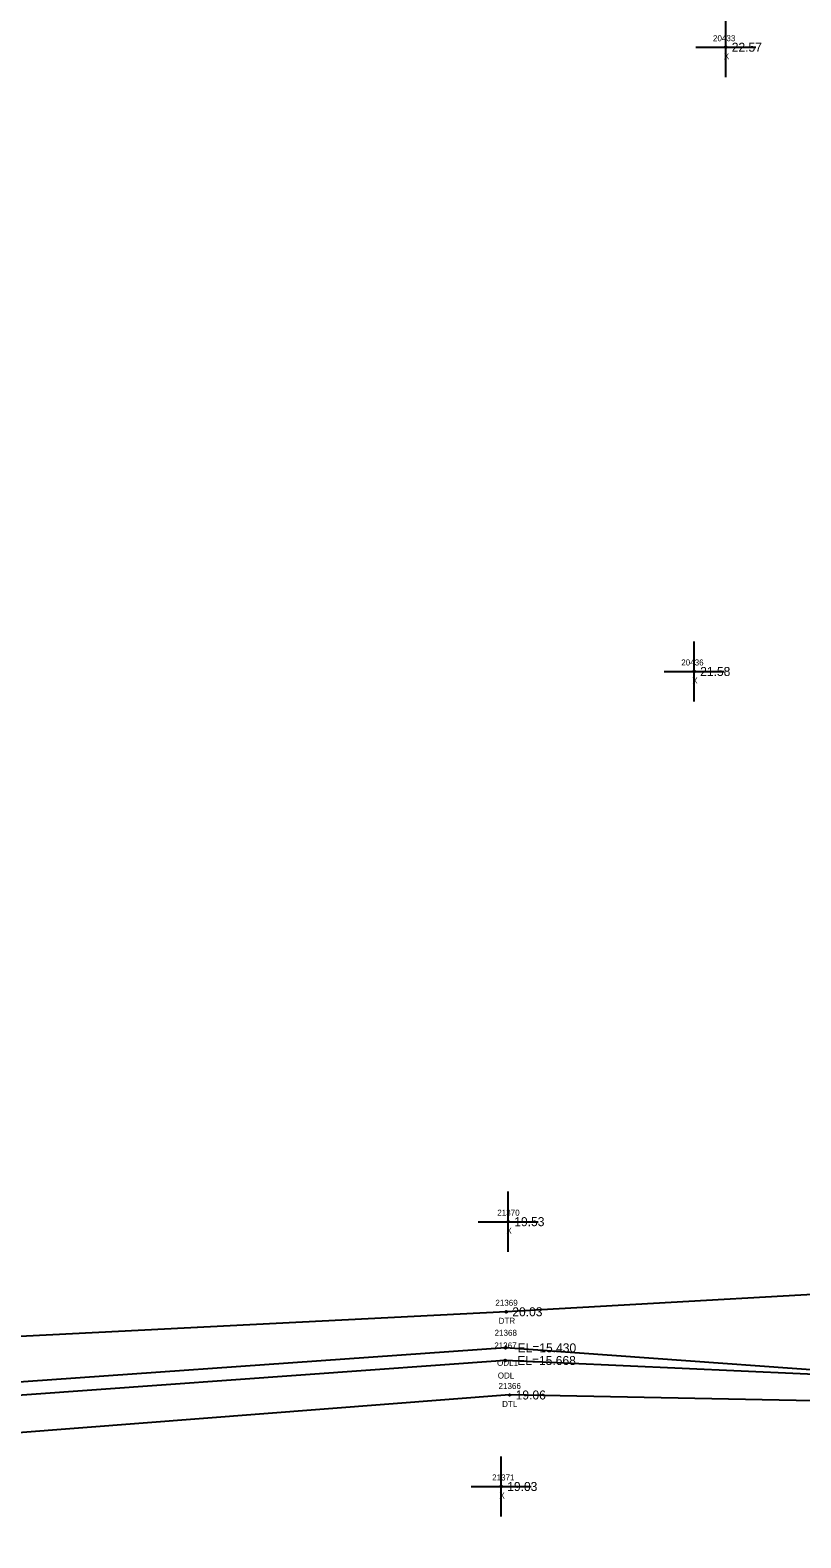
# Model space of a CAD drawing. Extents: x 2655177 to 2656219, y 761780 to 764748.
# Drawn here: x 2655601.7 to 2655730, y 763539 to 763790 of the extents above; entities that cross this region are included whole.
import ezdxf

# ---------------------------------------------------------------- set-up
doc = ezdxf.new("R2010")
doc.units = 0
for name, color, linetype in [('RD_EX_H2O', 7, 'Continuous'), ('RD_EX_H2O_txCode', 7, 'Continuous'), ('RD_EX_Misc', 7, 'Continuous'), ('RD_EX_Misc_txCode', 7, 'Continuous'), ('RD_EX_TX_H2O_ELEV', 7, 'Continuous'), ('RD_EX_TX_Misc_ELEV', 7, 'Continuous'), ('RD_SMD_Locator', 7, 'Continuous')]:
    doc.layers.add(name, color=color, linetype=linetype)

msp = doc.modelspace()

# ---------------------------------------------------------------- linework, layer by layer
at = {"layer": 'RD_EX_H2O'}
for points in [[(2655757.45, 763580.99), (2655680.96, 763576.66), (2655578.06, 763571.44), (2655470.41, 763559.47), (2655370.94, 763554.75), (2655276.75, 763546.33)], [(2655759.35, 763565.01), (2655680.83, 763570.66), (2655578.54, 763563.45), (2655471.45, 763555.87), (2655371.16, 763549.76), (2655277.06, 763543.35)], [(2655759.35, 763565.01), (2655680.78, 763568.55), (2655578.67, 763561.21), (2655471.72, 763553.89), (2655371.24, 763547.95), (2655277.37, 763540.37)], [(2655751.61, 763561.47), (2655681.52, 763562.81), (2655578.85, 763554.88), (2655473.08, 763549.56), (2655371.46, 763543.69), (2655277.89, 763535.39)]]:
    msp.add_lwpolyline(points, dxfattribs=at)
at = {"layer": 'RD_EX_Misc'}
for p, q in [((2655717.48, 763782.15), (2655717.48, 763792.15)), ((2655712.48, 763787.15), (2655722.48, 763787.15)), ((2655712.23, 763678.24), (2655712.23, 763688.24)), ((2655707.23, 763683.24), (2655717.23, 763683.24)), ((2655681.29, 763586.66), (2655681.29, 763596.66)), ((2655676.29, 763591.66), (2655686.29, 763591.66)), ((2655680.11, 763542.58), (2655680.11, 763552.58)), ((2655675.11, 763547.58), (2655685.11, 763547.58))]:
    msp.add_line(p, q, dxfattribs=at)
at = {"layer": 'RD_SMD_Locator'}
for centre in [(2655717.48, 763787.15), (2655712.23, 763683.24), (2655681.29, 763591.66), (2655680.96, 763576.66), (2655680.78, 763568.55), (2655680.83, 763570.66), (2655681.52, 763562.81), (2655680.11, 763547.58)]:
    msp.add_circle(centre, 0.15, dxfattribs=at)

# ---------------------------------------------------------------- texts
at = {"layer": 'RD_EX_H2O_txCode'}
for s, p in [('21369', (2655679.14, 763577.66)), ('21368', (2655679.01, 763572.66)), ('DTR', (2655679.69, 763574.66)), ('21367', (2655678.96, 763570.55)), ('ODL1', (2655679.42, 763567.66)), ('ODL', (2655679.54, 763565.55)), ('21366', (2655679.67, 763563.81)), ('DTL', (2655680.27, 763560.81))]:
    msp.add_text(s, height=1, dxfattribs=at).set_placement(p)
at = {"layer": 'RD_EX_Misc_txCode'}
for s, p in [('20433', (2655715.36, 763788.15)), ('X', (2655717.17, 763785.15)), ('20436', (2655710.08, 763684.24)), ('X', (2655711.91, 763681.24)), ('21370', (2655679.46, 763592.66)), ('X', (2655680.98, 763589.66)), ('21371', (2655678.6, 763548.58)), ('X', (2655679.8, 763545.58))]:
    msp.add_text(s, height=1, dxfattribs=at).set_placement(p)
at = {"layer": 'RD_EX_TX_H2O_ELEV'}
for s, p in [('20.03', (2655681.96, 763575.91)), ('EL=15.430', (2655682.83, 763569.91)), ('EL=15.668', (2655682.78, 763567.8)), ('19.06', (2655682.52, 763562.06))]:
    msp.add_text(s, height=1.5, dxfattribs=at).set_placement(p)
at = {"layer": 'RD_EX_TX_Misc_ELEV'}
for s, p in [('22.57', (2655718.48, 763786.4)), ('21.58', (2655713.23, 763682.49)), ('19.53', (2655682.29, 763590.91)), ('19.03', (2655681.11, 763546.83))]:
    msp.add_text(s, height=1.5, dxfattribs=at).set_placement(p)

doc.saveas('drawing.dxf')
